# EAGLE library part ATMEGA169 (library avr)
MICROCONTROLLER 16 Kbytes FLASH 1 Kbytes SRAM 512 bytes EEPROM USART 8-channel 10 bit ADC 4x25 Segment LCD Driver
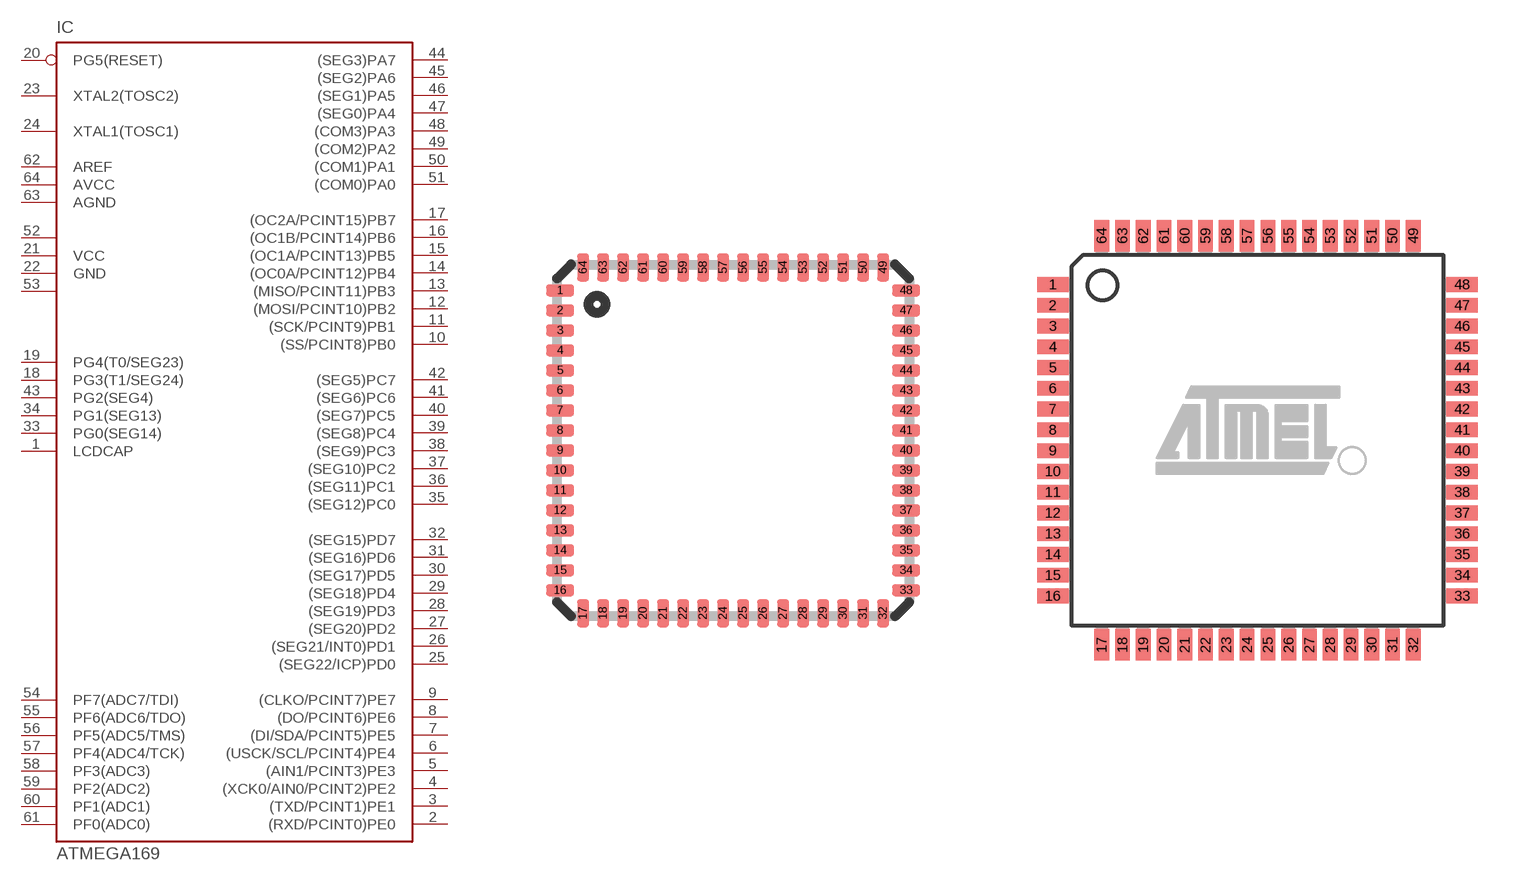
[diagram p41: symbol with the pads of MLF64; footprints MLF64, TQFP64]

Designator prefix IC

## ATMEGA169-16M, ATMEGA169V-8M  [MLF64]
1  LCDCAP  in
2  (RXD/PCINT0)PE0
3  (TXD/PCINT1)PE1
4  (XCK0/AIN0/PCINT2)PE2
5  (AIN1/PCINT3)PE3
6  (USCK/SCL/PCINT4)PE4
7  (DI/SDA/PCINT5)PE5
8  (DO/PCINT6)PE6
9  (CLKO/PCINT7)PE7
10  (SS/PCINT8)PB0
11  (SCK/PCINT9)PB1
12  (MOSI/PCINT10)PB2
13  (MISO/PCINT11)PB3
14  (OC0A/PCINT12)PB4
15  (OC1A/PCINT13)PB5
16  (OC1B/PCINT14)PB6
17  (OC2A/PCINT15)PB7
18  PG3(T1/SEG24)
19  PG4(T0/SEG23)
20  PG5(RESET)  in
21  VCC  pwr
22  GND  pwr
23  XTAL2(TOSC2)
24  XTAL1(TOSC1)
25  (SEG22/ICP)PD0
26  (SEG21/INT0)PD1
27  (SEG20)PD2
28  (SEG19)PD3
29  (SEG18)PD4
30  (SEG17)PD5
31  (SEG16)PD6
32  (SEG15)PD7
33  PG0(SEG14)
34  PG1(SEG13)
35  (SEG12)PC0  out
36  (SEG11)PC1  out
37  (SEG10)PC2  out
38  (SEG9)PC3  out
39  (SEG8)PC4  out
40  (SEG7)PC5  out
41  (SEG6)PC6  out
42  (SEG5)PC7  out
43  PG2(SEG4)
44  (SEG3)PA7
45  (SEG2)PA6
46  (SEG1)PA5
47  (SEG0)PA4
48  (COM3)PA3
49  (COM2)PA2
50  (COM1)PA1
51  (COM0)PA0
52  VCC1  pwr
53  GND1  pwr
54  PF7(ADC7/TDI)  in
55  PF6(ADC6/TDO)  in
56  PF5(ADC5/TMS)  in
57  PF4(ADC4/TCK)  in
58  PF3(ADC3)  in
59  PF2(ADC2)  in
60  PF1(ADC1)  in
61  PF0(ADC0)  in
62  AREF
63  AGND
64  AVCC

## ATMEGA169-16A, ATMEGA169V-8A  [TQFP64]
Pads as for MLF64

## Footprint MLF64 (pad centres in mm)
64M1 Micro Lead Frame package (MLF)
smd 0.7 x 0.3: 1 -4.325,3.75; 2 -4.325,3.25; 3 -4.325,2.75; 4 -4.325,2.25; 5 -4.325,1.75; 6 -4.325,1.25; 7 -4.325,0.75; 8 -4.325,0.25; 9 -4.325,-0.25; 10 -4.325,-0.75; 11 -4.325,-1.25; 12 -4.325,-1.75; 13 -4.325,-2.25; 14 -4.325,-2.75; 15 -4.325,-3.25; 16 -4.325,-3.75; 33 4.325,-3.75; 34 4.325,-3.25; 35 4.325,-2.75; 36 4.325,-2.25; 37 4.325,-1.75; 38 4.325,-1.25; 39 4.325,-0.75; 40 4.325,-0.25; 41 4.325,0.25; 42 4.325,0.75; 43 4.325,1.25; 44 4.325,1.75; 45 4.325,2.25; 46 4.325,2.75; 47 4.325,3.25; 48 4.325,3.75
smd 0.3 x 0.7: 17 -3.75,-4.325; 18 -3.25,-4.325; 19 -2.75,-4.325; 20 -2.25,-4.325; 21 -1.75,-4.325; 22 -1.25,-4.325; 23 -0.75,-4.325; 24 -0.25,-4.325; 25 0.25,-4.325; 26 0.75,-4.325; 27 1.25,-4.325; 28 1.75,-4.325; 29 2.25,-4.325; 30 2.75,-4.325; 31 3.25,-4.325; 32 3.75,-4.325; 49 3.75,4.325; 50 3.25,4.325; 51 2.75,4.325; 52 2.25,4.325; 53 1.75,4.325; 54 1.25,4.325; 55 0.75,4.325; 56 0.25,4.325; 57 -0.25,4.325; 58 -0.75,4.325; 59 -1.25,4.325; 60 -1.75,4.325; 61 -2.25,4.325; 62 -2.75,4.325; 63 -3.25,4.325; 64 -3.75,4.325

## Footprint TQFP64 (pad centres in mm)
Thin Plasic Quad Flat Package
smd 1.194 x 0.559: 1 -7.76,5.905; 2 -7.76,5.118; 3 -7.76,4.331; 4 -7.76,3.543; 5 -7.76,2.756; 6 -7.76,1.968; 7 -7.76,1.181; 8 -7.76,0.394; 9 -7.76,-0.394; 10 -7.76,-1.181; 11 -7.76,-1.968; 12 -7.76,-2.756; 13 -7.76,-3.543; 14 -7.76,-4.331; 15 -7.76,-5.118; 16 -7.76,-5.905; 33 7.76,-5.905; 34 7.76,-5.118; 35 7.76,-4.331; 36 7.76,-3.543; 37 7.76,-2.756; 38 7.76,-1.968; 39 7.76,-1.181; 40 7.76,-0.394; 41 7.76,0.394; 42 7.76,1.181; 43 7.76,1.968; 44 7.76,2.756; 45 7.76,3.543; 46 7.76,4.331; 47 7.76,5.118; 48 7.76,5.905
smd 0.559 x 1.194: 17 -5.905,-7.76; 18 -5.118,-7.76; 19 -4.331,-7.76; 20 -3.543,-7.76; 21 -2.756,-7.76; 22 -1.968,-7.76; 23 -1.181,-7.76; 24 -0.394,-7.76; 25 0.394,-7.76; 26 1.181,-7.76; 27 1.968,-7.76; 28 2.756,-7.76; 29 3.543,-7.76; 30 4.331,-7.76; 31 5.118,-7.76; 32 5.905,-7.76; 49 5.905,7.76; 50 5.118,7.76; 51 4.331,7.76; 52 3.543,7.76; 53 2.756,7.76; 54 1.968,7.76; 55 1.181,7.76; 56 0.394,7.76; 57 -0.394,7.76; 58 -1.181,7.76; 59 -1.968,7.76; 60 -2.756,7.76; 61 -3.543,7.76; 62 -4.331,7.76; 63 -5.118,7.76; 64 -5.905,7.76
